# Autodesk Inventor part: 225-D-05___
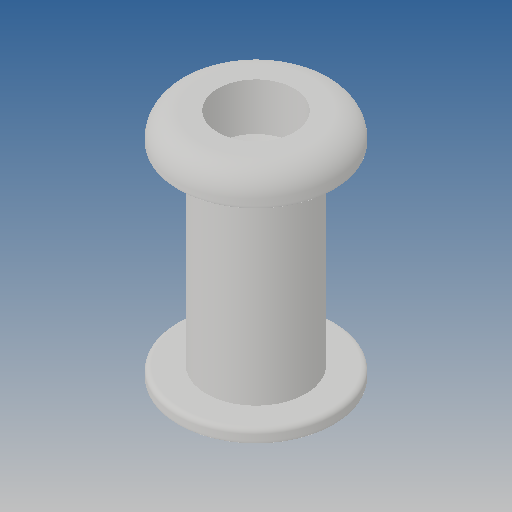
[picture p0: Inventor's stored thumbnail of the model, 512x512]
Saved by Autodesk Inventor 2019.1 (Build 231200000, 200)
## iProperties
Created: 2010-06
Part Number: 225-D-05___
Material: Ogólny
Document SubType Name: Modeling
Designer: CADENGINEERING4
Density: 1 g/cm^3
Appearance: Domyślna
Author: CADENGINEERING4
Revision Number: ANY
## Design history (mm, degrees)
feature "NONE"
node "Bryła1"
